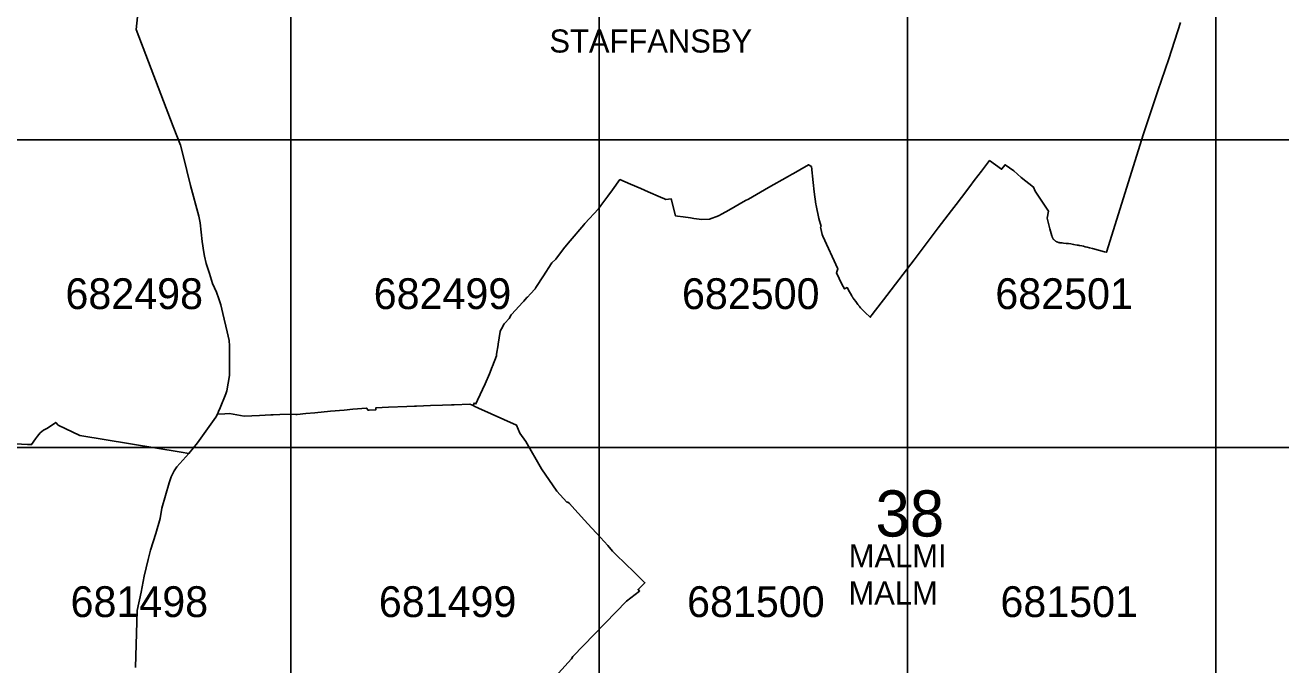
# Model space of a CAD drawing. Extents: x 25485000 to 25520000, y 6656775 to 6690000.
# Drawn here: x 25498138 to 25502211, y 6681295 to 6683372 of the extents above; entities that cross this region are included whole.
import ezdxf

# ---------------------------------------------------------------- set-up
doc = ezdxf.new("R2010")
doc.units = 0
doc.layers.add('Level 63', color=7, linetype='Continuous')

msp = doc.modelspace()

# ---------------------------------------------------------------- linework, layer by layer
at = {"layer": 'Level 63'}
for points in [[(25498000, 6683000), (25499000, 6683000), (25499000, 6684000), (25498000, 6684000)], [(25499000, 6683000), (25500000, 6683000), (25500000, 6684000), (25499000, 6684000)], [(25500000, 6683000), (25501000, 6683000), (25501000, 6684000), (25500000, 6684000)], [(25501000, 6683000), (25502000, 6683000), (25502000, 6684000), (25501000, 6684000)], [(25502000, 6683000), (25503000, 6683000), (25503000, 6684000), (25502000, 6684000)], [(25498000, 6682000), (25499000, 6682000), (25499000, 6683000), (25498000, 6683000)], [(25499000, 6682000), (25500000, 6682000), (25500000, 6683000), (25499000, 6683000)], [(25500000, 6682000), (25501000, 6682000), (25501000, 6683000), (25500000, 6683000)], [(25501000, 6682000), (25502000, 6682000), (25502000, 6683000), (25501000, 6683000)], [(25502000, 6682000), (25503000, 6682000), (25503000, 6683000), (25502000, 6683000)], [(25498000, 6681000), (25499000, 6681000), (25499000, 6682000), (25498000, 6682000)], [(25499000, 6681000), (25500000, 6681000), (25500000, 6682000), (25499000, 6682000)], [(25500000, 6681000), (25501000, 6681000), (25501000, 6682000), (25500000, 6682000)], [(25501000, 6681000), (25502000, 6681000), (25502000, 6682000), (25501000, 6682000)], [(25502000, 6681000), (25503000, 6681000), (25503000, 6682000), (25502000, 6682000)]]:
    msp.add_lwpolyline(points, close=True, dxfattribs=at)
for points in [[(25498009.3, 6682017.8), (25498145.5, 6682010.5), (25498158.5, 6682009.8), (25498170.9, 6682028.5), (25498177.7, 6682036.9), (25498186.7, 6682048.1), (25498197.5, 6682057), (25498210.6, 6682063.2), (25498237.1, 6682082.2), (25498244.9, 6682073.2), (25498315.2, 6682039.2), (25498643.9, 6681985.2), (25498668.6, 6681981.2), (25498697.3, 6682016.2), (25498756.4, 6682099.1), (25498761.7, 6682109.3), (25498765.1, 6682116.9), (25498770.6, 6682129), (25498788.5, 6682175), (25498791.5, 6682184.3), (25498800.4, 6682233.8), (25498801.2, 6682330.8), (25498799.9, 6682347.8), (25498793.5, 6682375.6), (25498778.6, 6682435.8), (25498772.1, 6682463.5), (25498766.4, 6682483.3), (25498758.1, 6682504.5), (25498745.7, 6682532.6), (25498736.3, 6682565.3), (25498725.5, 6682598.3), (25498719.5, 6682622.3), (25498716.9, 6682633.8), (25498711.9, 6682669.7), (25498705, 6682729.6), (25498700.7, 6682751.4), (25498673.8, 6682850.7), (25498650.7, 6682948.4), (25498641.7, 6682981.9), (25498618.1, 6683043), (25498498.1, 6683357.9), (25498516.5, 6683535.4)], [(25498516.5, 6683535.4), (25498498.1, 6683357.9), (25498618.1, 6683043), (25498641.7, 6682981.9), (25498650.7, 6682948.4), (25498673.8, 6682850.7), (25498700.7, 6682751.4), (25498705, 6682729.6), (25498711.9, 6682669.7), (25498716.9, 6682633.8), (25498719.5, 6682622.3), (25498725.5, 6682598.3), (25498736.3, 6682565.3), (25498745.7, 6682532.6), (25498758.1, 6682504.5), (25498766.4, 6682483.3), (25498772.1, 6682463.5), (25498778.6, 6682435.8), (25498793.5, 6682375.6), (25498799.9, 6682347.8), (25498801.2, 6682330.8), (25498800.4, 6682233.8), (25498791.5, 6682184.3), (25498788.5, 6682175), (25498770.6, 6682129), (25498765.1, 6682116.9), (25498761.7, 6682109.3), (25498785.8, 6682110.1), (25498800.9, 6682110.7), (25498847.8, 6682102.6), (25498897.8, 6682104.7), (25498934.8, 6682106.2), (25498941.8, 6682106.5), (25498964.3, 6682107.4), (25498998.2, 6682108.8), (25499016.2, 6682107.8), (25499019.7, 6682108.1), (25499048.7, 6682110.7), (25499077.4, 6682113.3), (25499128.7, 6682118), (25499172.4, 6682121.9), (25499200.4, 6682124.5), (25499245.3, 6682128.5), (25499250.4, 6682121.5), (25499253.9, 6682121.6), (25499274.9, 6682122.5), (25499275.9, 6682129.4), (25499316.1, 6682131), (25499375.5, 6682133.4), (25499401.1, 6682134.4), (25499407.1, 6682134.6), (25499452.6, 6682136.4), (25499491.6, 6682137.9), (25499520.7, 6682139.1), (25499529.6, 6682139.4), (25499579.9, 6682141.4), (25499590.7, 6682136.6), (25499594.2, 6682144.8), (25499600.2, 6682142.1), (25499605.6, 6682153.9), (25499630, 6682207.1), (25499643.8, 6682239.9), (25499653.1, 6682262), (25499654.2, 6682264.5), (25499666.5, 6682298.4), (25499667.3, 6682303.7), (25499672.1, 6682334.1), (25499672.3, 6682335.7), (25499678.8, 6682377.4), (25499679.3, 6682380.3), (25499683.3, 6682386.1), (25499692.2, 6682402.4), (25499694.2, 6682404.6), (25499707.8, 6682419.5), (25499714, 6682430.9), (25499716.7, 6682433.8), (25499751.1, 6682471.2), (25499755.2, 6682475.7), (25499765.7, 6682487.1), (25499767.4, 6682489), (25499776.7, 6682499.2), (25499792, 6682515.8), (25499794.8, 6682519.8), (25499819.1, 6682557.4), (25499844.3, 6682596.4), (25499846.4, 6682599.6), (25499859.5, 6682611.8), (25499883.8, 6682645.5), (25499899, 6682663.6), (25499905.7, 6682671.5), (25499950.4, 6682723.8), (25499953.8, 6682727.4), (25499997.7, 6682775.1), (25500005.5, 6682785.9), (25500012.3, 6682795.2), (25500027.6, 6682816.2), (25500042.9, 6682837.3), (25500067.1, 6682870.4), (25500101.4, 6682855.7), (25500135.5, 6682841), (25500159, 6682830.8), (25500198.9, 6682813.6), (25500211.6, 6682808.1), (25500216.7, 6682805.9), (25500233.6, 6682807.9), (25500247.1, 6682753.1), (25500253.5, 6682752.1), (25500272.1, 6682749.4), (25500296.4, 6682745.9), (25500307, 6682744.4), (25500333.2, 6682740.6), (25500357.6, 6682742), (25500387, 6682752.2), (25500398.7, 6682758.8), (25500421, 6682771.5), (25500474.8, 6682802.2), (25500483.9, 6682807.3), (25500549.5, 6682844.7), (25500610.7, 6682879.5), (25500626.4, 6682888.4), (25500630.3, 6682890.7), (25500651.2, 6682902.6), (25500678.9, 6682918.4), (25500688.4, 6682912.6), (25500693.7, 6682860.9), (25500697.6, 6682831), (25500702.9, 6682790.2), (25500704, 6682786.3), (25500712.6, 6682743.6), (25500719.8, 6682718.4), (25500718.1, 6682716.1), (25500718.9, 6682712), (25500722.8, 6682691.9), (25500725.3, 6682686.4), (25500774.1, 6682580.2), (25500770.2, 6682568.1), (25500787.3, 6682531.3), (25500795.9, 6682515.5), (25500804, 6682520), (25500811.7, 6682505.9), (25500815, 6682500.1), (25500816.9, 6682496.9), (25500820, 6682491.8), (25500821.5, 6682489.4), (25500822, 6682488.6), (25500822, 6682488.6), (25500822, 6682488.6), (25500822, 6682488.6), (25500822.1, 6682488.5), (25500822.4, 6682488), (25500822.7, 6682487.5), (25500822.9, 6682487.3), (25500823.2, 6682486.8), (25500824.1, 6682485.4), (25500827.1, 6682481), (25500832, 6682474.1), (25500839.4, 6682464.5), (25500842, 6682461.3), (25500842.7, 6682460.5), (25500843.6, 6682459.5), (25500845, 6682457.8), (25500848, 6682454.3), (25500849.9, 6682452.2), (25500853.8, 6682448), (25500857, 6682444.7), (25500862.6, 6682439.1), (25500879.3, 6682423.7), (25500886, 6682432.4), (25500933.4, 6682494.6), (25500961.4, 6682531.3), (25501021.8, 6682610.4), (25501092.6, 6682704.8), (25501099.6, 6682713.5), (25501142.4, 6682769.6), (25501157.6, 6682789.6), (25501174.8, 6682812.2), (25501202.4, 6682848.3), (25501216.8, 6682867.2), (25501240.1, 6682897.8), (25501266.3, 6682932.2), (25501305.1, 6682904.2), (25501316.8, 6682918.6), (25501345.2, 6682899), (25501369.4, 6682876.7), (25501409.4, 6682846.1), (25501414.8, 6682832.8), (25501457.7, 6682767.4), (25501453.5, 6682744.8), (25501462.3, 6682710.9), (25501468.3, 6682687.8), (25501468.5, 6682687), (25501468.9, 6682685.9), (25501469.3, 6682684.8), (25501469.8, 6682683.5), (25501470.2, 6682682.6), (25501470.5, 6682681.9), (25501471.1, 6682680.8), (25501471.7, 6682679.7), (25501472.1, 6682679.2), (25501472.5, 6682678.6), (25501473.2, 6682677.5), (25501473.9, 6682676.6), (25501474.3, 6682676.2), (25501474.9, 6682675.5), (25501476, 6682674.3), (25501477.6, 6682672.8), (25501478.3, 6682672.2), (25501479.3, 6682671.4), (25501480.1, 6682670.8), (25501480.8, 6682670.3), (25501482.3, 6682669.4), (25501483.6, 6682668.7), (25501484.4, 6682668.3), (25501485.5, 6682667.8), (25501486.4, 6682667.4), (25501487.9, 6682666.9), (25501489.4, 6682666.4), (25501491, 6682666), (25501492.5, 6682665.7), (25501494.3, 6682665.5), (25501495.6, 6682665.4), (25501496.7, 6682665.3), (25501497.5, 6682665.3), (25501499.2, 6682665.2), (25501499.9, 6682665.1), (25501501.5, 6682664.9), (25501505.8, 6682664.5), (25501515.2, 6682663.4), (25501521.9, 6682662.6), (25501530, 6682661.4), (25501538.9, 6682660), (25501550.8, 6682657.9), (25501554.2, 6682657.3), (25501556.7, 6682656.8), (25501559.5, 6682656.3), (25501565.4, 6682655.1), (25501570.6, 6682653.9), (25501576.7, 6682652.6), (25501583.4, 6682651), (25501590.8, 6682649.2), (25501600.2, 6682646.6), (25501639.6, 6682636.3), (25501646, 6682634.7), (25501766.2, 6683018.6), (25501778.7, 6683058.4), (25501812.3, 6683158.3), (25501847.4, 6683262.5), (25501885.7, 6683380.5)], [(25501885.7, 6683380.5), (25501847.4, 6683262.5), (25501812.3, 6683158.3), (25501778.7, 6683058.4), (25501766.2, 6683018.6), (25501646, 6682634.7), (25501639.6, 6682636.3), (25501600.2, 6682646.6), (25501590.8, 6682649.2), (25501583.4, 6682651), (25501576.7, 6682652.6), (25501570.6, 6682653.9), (25501565.4, 6682655.1), (25501559.5, 6682656.3), (25501556.7, 6682656.8), (25501554.2, 6682657.3), (25501550.8, 6682657.9), (25501538.9, 6682660), (25501530, 6682661.4), (25501521.9, 6682662.6), (25501515.2, 6682663.4), (25501505.8, 6682664.5), (25501501.5, 6682664.9), (25501499.9, 6682665.1), (25501499.2, 6682665.2), (25501497.5, 6682665.3), (25501496.7, 6682665.3), (25501495.6, 6682665.4), (25501494.3, 6682665.5), (25501492.5, 6682665.7), (25501491, 6682666), (25501489.4, 6682666.4), (25501487.9, 6682666.9), (25501486.4, 6682667.4), (25501485.5, 6682667.8), (25501484.4, 6682668.3), (25501483.6, 6682668.7), (25501482.3, 6682669.4), (25501480.8, 6682670.3), (25501480.1, 6682670.8), (25501479.3, 6682671.4), (25501478.3, 6682672.2), (25501477.6, 6682672.8), (25501476, 6682674.3), (25501474.9, 6682675.5), (25501474.3, 6682676.2), (25501473.9, 6682676.6), (25501473.2, 6682677.5), (25501472.5, 6682678.6), (25501472.1, 6682679.2), (25501471.7, 6682679.7), (25501471.1, 6682680.8), (25501470.5, 6682681.9), (25501470.2, 6682682.6), (25501469.8, 6682683.5), (25501469.3, 6682684.8), (25501468.9, 6682685.9), (25501468.5, 6682687), (25501468.3, 6682687.8), (25501462.3, 6682710.9), (25501453.5, 6682744.8), (25501457.7, 6682767.4), (25501414.8, 6682832.8), (25501409.4, 6682846.1), (25501369.4, 6682876.7), (25501345.2, 6682899), (25501316.8, 6682918.6), (25501305.1, 6682904.2), (25501266.3, 6682932.2), (25501240.1, 6682897.8), (25501216.8, 6682867.2), (25501202.4, 6682848.3), (25501174.8, 6682812.2), (25501157.6, 6682789.6), (25501142.4, 6682769.6), (25501099.6, 6682713.5), (25501092.6, 6682704.8), (25501021.8, 6682610.4), (25500961.4, 6682531.3), (25500933.4, 6682494.6), (25500886, 6682432.4), (25500879.3, 6682423.7), (25500862.6, 6682439.1), (25500857, 6682444.7), (25500853.8, 6682448), (25500849.9, 6682452.2), (25500848, 6682454.3), (25500845, 6682457.8), (25500843.6, 6682459.5), (25500842.7, 6682460.5), (25500842, 6682461.3), (25500839.4, 6682464.5), (25500832, 6682474.1), (25500827.1, 6682481), (25500824.1, 6682485.4), (25500823.2, 6682486.8), (25500822.9, 6682487.3), (25500822.7, 6682487.5), (25500822.4, 6682488), (25500822.1, 6682488.5), (25500822, 6682488.6), (25500822, 6682488.6), (25500822, 6682488.6), (25500822, 6682488.6), (25500821.5, 6682489.4), (25500820, 6682491.8), (25500816.9, 6682496.9), (25500815, 6682500.1), (25500811.7, 6682505.9), (25500804, 6682520), (25500795.9, 6682515.5), (25500787.3, 6682531.3), (25500770.2, 6682568.1), (25500774.1, 6682580.2), (25500725.3, 6682686.4), (25500722.8, 6682691.9), (25500718.9, 6682712), (25500718.1, 6682716.1), (25500719.8, 6682718.4), (25500712.6, 6682743.6), (25500704, 6682786.3), (25500702.9, 6682790.2), (25500697.6, 6682831), (25500693.7, 6682860.9), (25500688.4, 6682912.6), (25500678.9, 6682918.4), (25500651.2, 6682902.6), (25500630.3, 6682890.7), (25500626.4, 6682888.4), (25500610.7, 6682879.5), (25500549.5, 6682844.7), (25500483.9, 6682807.3), (25500474.8, 6682802.2), (25500421, 6682771.5), (25500398.7, 6682758.8), (25500387, 6682752.2), (25500357.6, 6682742), (25500333.2, 6682740.6), (25500307, 6682744.4), (25500296.4, 6682745.9), (25500272.1, 6682749.4), (25500253.5, 6682752.1), (25500247.1, 6682753.1), (25500233.6, 6682807.9), (25500216.7, 6682805.9), (25500211.6, 6682808.1), (25500198.9, 6682813.6), (25500159, 6682830.8), (25500135.5, 6682841), (25500101.4, 6682855.7), (25500067.1, 6682870.4), (25500042.9, 6682837.3), (25500027.6, 6682816.2), (25500012.3, 6682795.2), (25500005.5, 6682785.9), (25499997.7, 6682775.1), (25499953.8, 6682727.4), (25499950.4, 6682723.8), (25499905.7, 6682671.5), (25499899, 6682663.6), (25499883.8, 6682645.5), (25499859.5, 6682611.8), (25499846.4, 6682599.6), (25499844.3, 6682596.4), (25499819.1, 6682557.4), (25499794.8, 6682519.8), (25499792, 6682515.8), (25499776.7, 6682499.2), (25499767.4, 6682489), (25499765.7, 6682487.1), (25499755.2, 6682475.7), (25499751.1, 6682471.2), (25499716.7, 6682433.8), (25499714, 6682430.9), (25499707.8, 6682419.5), (25499694.2, 6682404.6), (25499692.2, 6682402.4), (25499683.3, 6682386.1), (25499679.3, 6682380.3), (25499678.8, 6682377.4), (25499672.3, 6682335.7), (25499672.1, 6682334.1), (25499667.3, 6682303.7), (25499666.5, 6682298.4), (25499654.2, 6682264.5), (25499653.1, 6682262), (25499643.8, 6682239.9), (25499630, 6682207.1), (25499605.6, 6682153.9), (25499600.2, 6682142.1), (25499594.2, 6682144.8), (25499590.7, 6682136.6), (25499594.7, 6682134.8), (25499608.6, 6682128.7), (25499731.9, 6682073.3), (25499742.1, 6682046.7), (25499761.7, 6682020.2), (25499812.5, 6681931.1), (25499862.5, 6681859.1), (25499895.2, 6681823.5), (25499898.4, 6681823.5), (25499903.3, 6681818.2), (25499920.5, 6681799.4), (25499963.5, 6681752.4), (25500003.9, 6681708.4), (25500027.5, 6681682.6), (25500043.1, 6681664.1), (25500055.3, 6681652.2), (25500113.8, 6681595.3), (25500120.6, 6681588.6), (25500148.4, 6681561.6), (25500126.2, 6681539.5), (25500130.9, 6681534.6), (25500089, 6681501.7), (25499915, 6681322.2), (25499909.7, 6681313.9), (25499805, 6681198.4)], [(25498496.2, 6681285.8), (25498500.7, 6681471.6), (25498513.8, 6681530.9), (25498523.8, 6681582.6), (25498536.6, 6681636.6), (25498544.4, 6681667.5), (25498561.8, 6681720.8), (25498575.9, 6681770), (25498581.1, 6681804), (25498605.2, 6681886.3), (25498611.9, 6681905.3), (25498615.7, 6681914), (25498621.7, 6681925), (25498630.2, 6681938), (25498668.6, 6681981.2), (25498697.3, 6682016.2), (25498756.4, 6682099.1), (25498761.7, 6682109.3), (25498785.8, 6682110.1), (25498800.9, 6682110.7), (25498847.8, 6682102.6), (25498897.8, 6682104.7), (25498934.8, 6682106.2), (25498941.8, 6682106.5), (25498964.3, 6682107.4), (25498998.2, 6682108.8), (25499016.2, 6682107.8), (25499019.7, 6682108.1), (25499048.7, 6682110.7), (25499077.4, 6682113.3), (25499128.7, 6682118), (25499172.4, 6682121.9), (25499200.4, 6682124.5), (25499245.3, 6682128.5), (25499250.4, 6682121.5), (25499253.9, 6682121.6), (25499274.9, 6682122.5), (25499275.9, 6682129.4), (25499316.1, 6682131), (25499375.5, 6682133.4), (25499401.1, 6682134.4), (25499407.1, 6682134.6), (25499452.6, 6682136.4), (25499491.6, 6682137.9), (25499520.7, 6682139.1), (25499529.6, 6682139.4), (25499579.9, 6682141.4), (25499590.7, 6682136.6), (25499594.7, 6682134.8), (25499608.6, 6682128.7), (25499731.9, 6682073.3), (25499742.1, 6682046.7), (25499761.7, 6682020.2), (25499812.5, 6681931.1), (25499862.5, 6681859.1), (25499895.2, 6681823.5), (25499898.4, 6681823.5), (25499903.3, 6681818.2), (25499920.5, 6681799.4), (25499963.5, 6681752.4), (25500003.9, 6681708.4), (25500027.5, 6681682.6), (25500043.1, 6681664.1), (25500055.3, 6681652.2), (25500113.8, 6681595.3), (25500120.6, 6681588.6), (25500148.4, 6681561.6), (25500126.2, 6681539.5), (25500130.9, 6681534.6), (25500089, 6681501.7), (25499915, 6681322.2), (25499909.7, 6681313.9), (25499805, 6681198.4)], [(25498496.2, 6681285.8), (25498500.7, 6681471.6), (25498513.8, 6681530.9), (25498523.8, 6681582.6), (25498536.6, 6681636.6), (25498544.4, 6681667.5), (25498561.8, 6681720.8), (25498575.9, 6681770), (25498581.1, 6681804), (25498605.2, 6681886.3), (25498611.9, 6681905.3), (25498615.7, 6681914), (25498621.7, 6681925), (25498630.2, 6681938), (25498668.6, 6681981.2), (25498643.9, 6681985.2), (25498315.2, 6682039.2), (25498244.9, 6682073.2), (25498237.1, 6682082.2), (25498210.6, 6682063.2), (25498197.5, 6682057), (25498186.7, 6682048.1), (25498177.7, 6682036.9), (25498170.9, 6682028.5), (25498158.5, 6682009.8), (25498145.5, 6682010.5), (25498009.3, 6682017.8)]]:
    msp.add_lwpolyline(points, dxfattribs=at)

# ---------------------------------------------------------------- texts
for s, height, p in [('STAFFANSBY', 75, (25499838.5, 6683282.9)), ('682498', 100, (25498268.5, 6682450)), ('682499', 100, (25499268.5, 6682450)), ('682500', 100, (25500268.5, 6682450)), ('682501', 100, (25501285.1, 6682450)), ('38', 150, (25500896.2, 6681711.4)), ('MALMI', 75, (25500809.4, 6681611.4)), ('MALM', 75, (25500808.7, 6681490.6)), ('681498', 100, (25498285.1, 6681450)), ('681499', 100, (25499285.1, 6681450)), ('681500', 100, (25500285.1, 6681450)), ('681501', 100, (25501301.6, 6681450))]:
    msp.add_text(s, height=height, dxfattribs=at).set_placement(p)

doc.saveas('drawing.dxf')
